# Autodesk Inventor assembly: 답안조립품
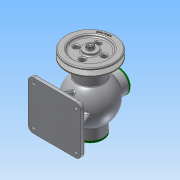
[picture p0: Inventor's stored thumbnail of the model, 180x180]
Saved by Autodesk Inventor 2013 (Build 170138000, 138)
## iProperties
Created: 2018-06
Part Number: 답안조립품
Document SubType Name: Assembly
Designer: Administrator
Author: Administrator
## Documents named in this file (19)
- C:\Users\Administrator\Desktop\480612V1003\답안조립품.iam
- C:\Users\Administrator\Desktop\480612V1003\본체.ipt
- C:\Users\Administrator\Desktop\480612V1003\V-벨트풀리.ipt
- C:\Users\Administrator\Desktop\480612V1003\너트 M8.ipt
- C:\Users\Administrator\Desktop\480612V1003\뒤커버.ipt
- C:\Users\Administrator\Desktop\480612V1003\멈춤링 15x1.ipt
- C:\Users\Administrator\Desktop\480612V1003\멈춤링 35x1.6.ipt
- 멈춤링 35x1.6.ipt
- C:\Users\Administrator\Desktop\480612V1003\베어링 6202.ipt
- 베어링 6202.ipt
- C:\Users\Administrator\Desktop\480612V1003\볼트 M4x12.ipt
- C:\Users\Administrator\Desktop\480612V1003\볼트 M4x16.ipt
- C:\Users\Administrator\Desktop\480612V1003\부시.ipt
- C:\Users\Administrator\Desktop\480612V1003\상부커버.ipt
- C:\Users\Administrator\Desktop\480612V1003\슬라이드.ipt
- C:\Users\Administrator\Desktop\480612V1003\앞커버.ipt
- C:\Users\Administrator\Desktop\480612V1003\오일 실 15 30 7.ipt
- C:\Users\Administrator\Desktop\480612V1003\키 4x4x12.ipt
- C:\Users\Administrator\Desktop\480612V1003\편심축.ipt
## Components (1 placed, 1 different names)
1. V-벨트풀리:1
